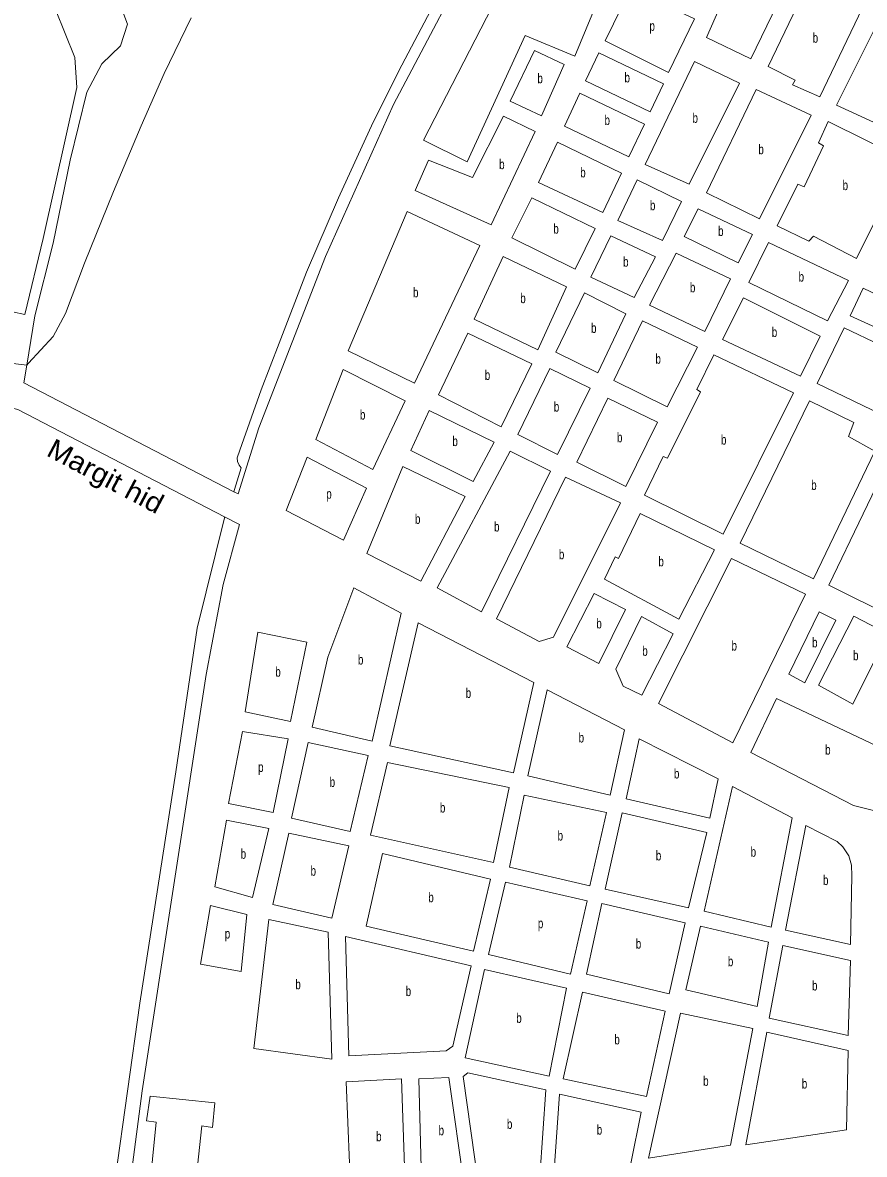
# Model space of a CAD drawing. Extents: x 639657 to 671642, y 222838 to 252123.
# Drawn here: x 649712 to 650572, y 240424 to 241581 of the extents above; entities that cross this region are included whole.
import ezdxf
from ezdxf.enums import TextEntityAlignment as Align

# ---------------------------------------------------------------- set-up
doc = ezdxf.new("R2010")
doc.units = 0
doc.header["$LTSCALE"] = 4
doc.layers.add('1', color=7, linetype='Continuous', lineweight=13)
doc.layers.add('5', color=7, linetype='Continuous', lineweight=13)
doc.layers.add('22', color=7, linetype='Continuous')
doc.layers.add('7', color=7, linetype='Continuous')

msp = doc.modelspace()

# ---------------------------------------------------------------- linework, layer by layer
at = {"layer": '1'}
for points in [[(649701.37, 241285.37), (649713.82, 241282.54), (649732.69, 241360.03), (649766.98, 241514.57), (649765.11, 241545.07), (649745.25, 241594.29), (649738.43, 241614.28), (649731.83, 241639.85), (649731.45, 241665.41), (649739.5, 241710.27), (649766.23, 241844.86), (649812.86, 242068.03), (649874.79, 242323.72), (649906.5, 242423.14), (650071.02, 242910.08)], [(649715.825, 241230.765), (649724.13, 241281.23), (649742.99, 241355.49), (649760.36, 241440.28), (649777.06, 241509.82), (649792.59, 241538.56), (649811.53, 241557.2), (649818.67, 241579.3), (649811.2, 241598.86), (649789.74, 241606.22), (649757.95, 241607.79), (649748.52, 241615.33), (649741.3, 241651), (649743.52, 241680.63), (649762.1, 241777.87), (649779.8, 241860.33), (649784.88, 241887.2), (649829.34, 242075.6), (649888.78, 242320.49), (649953.71, 242520.45), (650002.186, 242662.195)], [(650479.99, 242341.59), (650388.84, 242124.91), (650311.11, 241935.5), (650224.57, 241752.73), (650184.87, 241675.95), (650090.39, 241497.06), (650020.88, 241341.74), (649953.04, 241166.66), (649931.861, 241099.107), (649927.334, 241101.455)], [(649927.334, 241101.455), (649712.85, 241212.69), (649715.825, 241230.765)], [(649517.573, 241182.519), (649696.3, 241188.04), (649706.63, 241185.39), (649918.026, 241075.888)], [(649918.026, 241075.888), (649933.25, 241068.002), (649916.64, 241006.75), (649899.23, 240914.55), (649833.69, 240489.25), (649812, 240322.2), (649801.13, 240203.85), (649803.92, 240108.11), (649814.45, 239999.23), (649837.26, 239906.37), (649861.82, 239765.17), (649878.15, 239686.26), (649888.52, 239626.13), (649898.01, 239589.86), (649914.52, 239545.63), (649927.53, 239523.01), (649925.34, 239517.73), (649892.647, 239508.316)]]:
    msp.add_lwpolyline(points, dxfattribs=at)
for points in [[(650308.71, 241825.55), (650121.23, 241460.7), (650165.64, 241438.47), (650225, 241567.62), (650275.86, 241546.67), (650322.07, 241658.44), (650286.46, 241677.43), (650336.39, 241813.89)], [(650493.81, 241622.82), (650443.17, 241640.98), (650410.13, 241565.47), (650455.62, 241543.88)], [(650332.71, 241615.25), (650306.6, 241562.06), (650371.61, 241529.69), (650398.15, 241584.61)], [(650525.97, 241504.85), (650569.78, 241595.8), (650511.41, 241615.69), (650473.21, 241536.11), (650500.89, 241522.09), (650498.08, 241517.37)], [(650660.09, 241544.48), (650581.33, 241572.8), (650543.14, 241496.43), (650622.95, 241459.52)], [(650264.88, 241537.89), (650234.63, 241552.35), (650209.6, 241500.43), (650241.75, 241485.44)], [(650300.13, 241549.83), (650286.54, 241521.3), (650352.83, 241489.58), (650366.43, 241518.11)], [(650392.61, 241415.61), (650443.96, 241519), (650398.05, 241541.23), (650347.77, 241435.68)], [(650464.48, 241380.22), (650517.13, 241486.4), (650460.91, 241512.52), (650410.2, 241406.76)], [(650280.92, 241508.64), (650265.17, 241474.96), (650331.03, 241443.67), (650346.79, 241476.92)], [(650171.19, 241422.57), (650126.34, 241440.28), (650112.74, 241409.39), (650190.19, 241373.99), (650235.09, 241469.45), (650202.91, 241485.2)], [(650613.46, 241440.65), (650534.72, 241479.7), (650524.58, 241458.03), (650529.94, 241454.8), (650509.87, 241412.97), (650503.43, 241415.78), (650482.5, 241373.09), (650514.9, 241357.34), (650519.63, 241362.48), (650563.61, 241339.61)], [(650323.48, 241426.94), (650258.04, 241458.66), (650238.62, 241417.47), (650304.27, 241386.61)], [(650384.62, 241398.02), (650339.35, 241420.03), (650319.72, 241378.63), (650365.2, 241358.12)], [(650276, 241328.69), (650211.43, 241360.84), (650231.92, 241401.6), (650296.5, 241370.3)], [(650104.32, 241387.94), (650044.28, 241245.26), (650111.86, 241212.25), (650178.55, 241352.97)], [(650457.35, 241364.34), (650401.79, 241390.46), (650387.33, 241362.36), (650442.47, 241335.17)], [(650292.09, 241320.71), (650312.59, 241362.97), (650358.07, 241341.38), (650336.29, 241299.77)], [(650555.18, 241317.3), (650473.66, 241356.15), (650453.59, 241315.18), (650533.83, 241276.12)], [(650202.58, 241341.75), (650172.79, 241277.82), (650237.8, 241246.53), (650267.15, 241310.67)], [(650434.7, 241319.08), (650379.35, 241345.2), (650351.95, 241292.22), (650408.59, 241265.24)], [(650327.87, 241283.04), (650285.61, 241304.62), (650256.26, 241243.91), (650299.38, 241222.76)], [(650570.41, 241309.32), (650643.79, 241274.36), (650631.27, 241247.54), (650557.03, 241281.22)], [(650447.97, 241299.51), (650526.27, 241260.24), (650506.21, 241219.49), (650426.61, 241256.83)], [(650345.04, 241276.13), (650315.47, 241214.99), (650370.18, 241188.24), (650401.03, 241249.15)], [(650523.37, 241212.15), (650550.99, 241268.99), (650625.22, 241233.6), (650597.6, 241176.11)], [(650231.75, 241232.15), (650166.31, 241263.45), (650136.53, 241200.38), (650200.46, 241167.8)], [(650427.44, 241057.96), (650346.99, 241097.88), (650365.98, 241137.35), (650370.28, 241135.84), (650404.15, 241203.62), (650400.51, 241205.99), (650417.77, 241241.17), (650499.29, 241202.54)], [(650102.58, 241194.45), (650039.08, 241226.16), (650011, 241154.93), (650069.35, 241124.08)], [(650217.62, 241160.03), (650250.21, 241227.17), (650291.4, 241207.1), (650257.96, 241139.32)], [(650327.9, 241106.73), (650277.7, 241131.54), (650309.63, 241197.18), (650360.05, 241172.58)], [(650560.87, 241172.11), (650515.6, 241194.13), (650444.6, 241048.9), (650519.69, 241012.22), (650582.28, 241142.86), (650555.25, 241157.74)], [(650193.34, 241152.14), (650127.04, 241184.29), (650108.05, 241143.54), (650171.98, 241111.82)], [(650605.49, 241151.61), (650535.14, 241005.74), (650603.15, 240972.08), (650673.5, 241117.95)], [(650180.48, 240978.65), (650135.01, 241003.24), (650209.64, 241142.87), (650250.83, 241122.37)], [(650002.15, 241136.7), (649980.76, 241082.2), (650039.54, 241051.78), (650062.86, 241105.2)], [(650163.57, 241096.59), (650100.07, 241127.23), (650063.35, 241038.2), (650118.48, 241009.94)], [(650195.72, 240971.53), (650266.06, 241116.32), (650322.28, 241089.99), (650254.09, 240952.92), (650239.26, 240948.45)], [(650381.93, 240971.31), (650306.2, 241012.07), (650316.99, 241034.81), (650320.21, 241033.09), (650342.65, 241078.99), (650418.6, 241042.09)], [(650437.26, 240844.9), (650361.32, 240885.02), (650435.76, 241033.25), (650511.28, 240996.78)], [(650023.55, 240932.33), (650049.885, 241003.07), (650098.38, 240977.29), (650068.69, 240846.53), (650007.51, 240860.83)], [(650295.65, 240997.49), (650267.6, 240942.8), (650300.42, 240925.97), (650327.61, 240981.1)], [(650542.36, 240970.29), (650525.2, 240978.7), (650494.34, 240914.78), (650510.64, 240905.94)], [(650086.93, 240841.76), (650115.54, 240967.37), (650233.97, 240906.34), (650212.95, 240814.01)], [(650317.8, 240919.92), (650343.92, 240973.97), (650376.31, 240956.29), (650344.16, 240893.44), (650325.07, 240902.72)], [(650524.6, 240903.54), (650560.84, 240974.11), (650595.59, 240956.2), (650559.78, 240884.13)], [(649939.03, 240876.44), (649952.08, 240958.04), (650002.1, 240947.63), (649985.18, 240866.68)], [(650227.76, 240811.19), (650247.48, 240899.01), (650326.65, 240858.03), (650311.91, 240791.25)], [(650481.83, 240890.11), (650640.8, 240814.79), (650632.39, 240800.42), (650613.03, 240783.72), (650603.14, 240779.02), (650591.53, 240775.39), (650579.5, 240775.85), (650560.4, 240780.62), (650455.71, 240834.98)], [(649922.01, 240782.94), (649936.42, 240856.39), (649982.86, 240848.99), (649967.74, 240773.57)], [(649986.48, 240767.64), (650003.41, 240845.251), (650064.58, 240831.71), (650046.38, 240754.2)], [(650328.3, 240787.6), (650341.52, 240848.8), (650422.19, 240807.82), (650413.73, 240767.88)], [(650067.11, 240750.41), (650084.4, 240824.84), (650208.61, 240799.21), (650192.77, 240722.31)], [(650407.96, 240672.74), (650436.99, 240800.27), (650497.71, 240768.14), (650476.22, 240656.49)], [(650209.1, 240717.57), (650224.07, 240791.43), (650308.01, 240773.43), (650291.1, 240698.49)], [(650306.85, 240695.28), (650324.19, 240773.22), (650410.48, 240753.07), (650391.86, 240675.99)], [(649907.97, 240697.66), (649919.85, 240765.69), (649963.06, 240757.31), (649946.5, 240686.82)], [(650557.37, 240638.71), (650491.03, 240653.24), (650511.65, 240760.17), (650543.62, 240743.99), (650549.62, 240738.4), (650555.61, 240729.15), (650558.39, 240719.9), (650558.79, 240708.73)], [(649967.19, 240679.61), (649983.66, 240752.4), (650044.84, 240739.39), (650027.51, 240665.52)], [(650062.72, 240657.5), (650172.2, 240631.93), (650189.53, 240705.58), (650079.19, 240731.8)], [(650187.66, 240628.46), (650271.16, 240608.31), (650288.5, 240683.46), (650204.99, 240702.32)], [(649893.4, 240618.54), (649903.62, 240678.67), (649940.75, 240669.35), (649935.05, 240610.94)], [(650372.28, 240588.34), (650388.53, 240660.7), (650303.31, 240680.64), (650287.7, 240608.28)], [(650027.65, 240521.6), (650023.83, 240651.14), (649963.08, 240664.37), (649947.99, 240532.5)], [(650462.03, 240575.48), (650473.76, 240640.98), (650404.2, 240657.45), (650389.25, 240592.39)], [(650151.17, 240534.88), (650169.81, 240616.9), (650041.43, 240647.02), (650044.84, 240525), (650144.29, 240530.17)], [(650554.96, 240545.65), (650557.48, 240622.33), (650488.35, 240637.73), (650474.24, 240563.43)], [(650249.47, 240503.96), (650267.27, 240594.14), (650183.33, 240613.22), (650163.82, 240522.82)], [(650348.87, 240483.35), (650367.93, 240570.44), (650283.47, 240589.83), (650263.85, 240501.35)], [(650457.47, 240552.72), (650383.62, 240568.34), (650350.89, 240420.19), (650434.89, 240433.55)], [(650554.93, 240530.4), (650471.85, 240549.04), (650450.35, 240433.94), (650553.26, 240449.2)], [(650246.22, 240490.22), (650166.36, 240507.56), (650161.84, 240503.71), (650177.3, 240392.83), (650240.03, 240401.51)], [(650041.99, 240498.37), (650047.42, 240373.59), (650102.77, 240381.72), (650098.7, 240501.47)], [(650147.02, 240502.88), (650116.23, 240501.55), (650119.29, 240384.57), (650162.9, 240390.5)], [(649816.2, 240253.51), (649813.42, 240229.05), (649878.2, 240221.16), (649881.04, 240245.43), (649872.24, 240246.74), (649880.33, 240317.83), (649931.86, 240311.71), (649934.22, 240329.73), (649939.62, 240329.2), (649942.91, 240358.51), (649937.66, 240359.3), (649939.73, 240377.42), (649887.33, 240383.55), (649894.79, 240453.34), (649905.52, 240451.82), (649907.93, 240476.95), (649842.01, 240483.53), (649838.3, 240458.4), (649847.97, 240457.09), (649840.73, 240381.47), (649826.12, 240382.81), (649820.62, 240330.7), (649834.55, 240328.66), (649824.78, 240252.85)], [(650343.68, 240467.24), (650260.17, 240485.89), (650254.42, 240402.98), (650332.84, 240414.85)]]:
    msp.add_lwpolyline(points, close=True, dxfattribs=at)
at = {"layer": '5'}
for p, q in [((650099.07, 241537.42), (650137.47, 241610.13)), ((649856.14, 241528.75), (649883.98, 241585.81)), ((650069.73, 241479.07), (650099.07, 241537.42)), ((649832.82, 241475.33), (649856.14, 241528.75)), ((649804.32, 241408.18), (649832.82, 241475.33)), ((650034.33, 241401.63), (650069.73, 241479.07)), ((649774.73, 241335.02), (649804.32, 241408.18)), ((650001.72, 241325.68), (650034.33, 241401.63)), ((649755.28, 241283.52), (649774.73, 241335.02)), ((649973.64, 241253.38), (650001.72, 241325.68)), ((649742.77, 241259.93), (649755.28, 241283.52)), ((649955.49, 241205.53), (649973.64, 241253.38)), ((649702.131, 241232.583), (649715.825, 241230.765)), ((649933.44, 241143.94), (649955.49, 241205.53)), ((649930.84, 241136.01), (649933.44, 241143.94)), ((649931.26, 241132.35), (649930.84, 241136.01)), ((649932.97, 241128.7), (649931.26, 241132.35)), ((649934.9, 241125.9), (649932.97, 241128.7)), ((649889.8, 240961.82), (649868.24, 240815.15)), ((649868.24, 240815.15), (649831.46, 240578.71)), ((649831.46, 240578.71), (649800.52, 240360.09))]:
    msp.add_line(p, q, dxfattribs=at)
for points in [[(649715.825, 241230.765), (649717.673, 241232.765), (649742.77, 241259.93)], [(649927.334, 241101.455), (649927.989, 241103.57), (649934.9, 241125.9)], [(649918.026, 241075.888), (649917.713, 241074.62), (649889.8, 240961.82)]]:
    msp.add_lwpolyline(points, dxfattribs=at)

# ---------------------------------------------------------------- texts
at = {"layer": '22', "width": 1.1}
msp.add_text('Margit hid', height=20, rotation=331.93, dxfattribs=at).set_placement((649791.73, 241108.47), align=Align.CENTER)
at = {"layer": '7', "width": 0.75}
for s, p in [('p', (650351.997, 241572.47)), ('b', (650518.736, 241560.27)), ('b', (650237.503, 241518.895)), ('b', (650326.485, 241519.705)), ('b', (650395.968, 241478.42)), ('b', (650306.078, 241476.155)), ('b', (650463.237, 241446.37)), ('b', (650198.422, 241431.081)), ('b', (650281.242, 241422.635)), ('b', (650549.298, 241409.655)), ('b', (650352.469, 241389.075)), ('b', (650253.777, 241365.145)), ('b', (650422.068, 241362.815)), ('b', (650325.046, 241331.37)), ('b', (650504.317, 241316.135)), ('b', (650393.326, 241305.22)), ('b', (650110.423, 241300.095)), ('b', (650219.99, 241294.14)), ('b', (650292.274, 241263.69)), ('b', (650476.926, 241259.5)), ('b', (650358.112, 241232.185)), ('b', (650183.722, 241215.625)), ('b', (650254.26, 241183.245)), ('b', (650056.206, 241175.12)), ('b', (650150.665, 241148.055)), ('b', (650318.805, 241151.955)), ('b', (650425.051, 241149.565)), ('b', (650517.2, 241103.175)), ('p', (650021.78, 241094.24)), ('b', (650112.44, 241068.585)), ('b', (650193.213, 241060.76)), ('b', (650259.453, 241032.385)), ('b', (650361.115, 241025.15)), ('b', (650297.683, 240961.73)), ('b', (650344.609, 240933.705)), ('b', (650435.811, 240939.075)), ('b', (650518.104, 240942.32)), ('b', (650054.161, 240924.8)), ('b', (650559.935, 240929.12)), ('b', (649969.751, 240912.36)), ('b', (650164.241, 240890.69)), ('b', (650279.592, 240845.13)), ('b', (650531.449, 240832.75)), ('p', (649952.169, 240814.98)), ('b', (650376.973, 240808.34)), ('b', (650025.274, 240799.725)), ('b', (650137.91, 240773.575)), ('b', (650258.119, 240744.96)), ('b', (649934.364, 240726.255)), ('b', (650358.489, 240724.605)), ('b', (650455.341, 240728.38)), ('b', (650005.766, 240708.96)), ('b', (650529.27, 240699.44)), ('b', (650126.035, 240681.865)), ('p', (650237.983, 240655.315)), ('p', (649918.109, 240644.805)), ('b', (650337.999, 240634.49)), ('b', (650432.076, 240616.465)), ('b', (649990.228, 240592.985)), ('b', (650102.962, 240586.01)), ('b', (650518.04, 240591.69)), ('b', (650215.896, 240558.59)), ('b', (650316.093, 240536.59)), ('b', (650406.825, 240494.265)), ('b', (650507.615, 240491.49)), ('b', (650206.364, 240450.195)), ('b', (650072.755, 240437.53)), ('b', (650136.561, 240443.725)), ('b', (650298.128, 240444.435))]:
    msp.add_text(s, height=10, dxfattribs=at).set_placement(p)

doc.saveas('drawing.dxf')
